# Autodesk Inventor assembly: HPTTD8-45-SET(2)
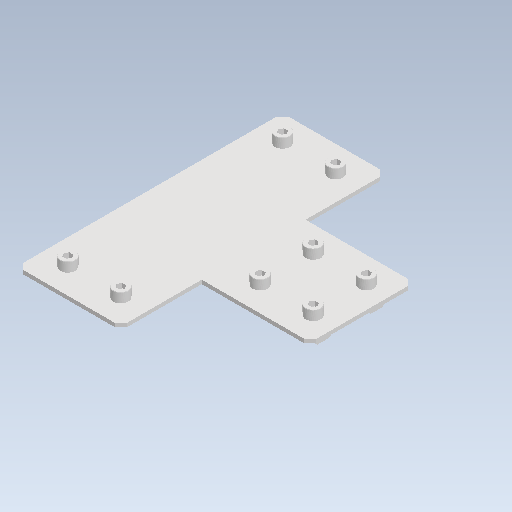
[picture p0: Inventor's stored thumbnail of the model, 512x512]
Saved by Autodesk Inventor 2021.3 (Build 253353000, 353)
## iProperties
Created: 2022-02
Part Number: HPTTD8-45-SET(2)
Document SubType Name: Assembly
Designer: kengo
Author: kengo
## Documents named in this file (4)
- C:\Users\kengo\Documents\S2S_frame\SDC345\frame_misumi_ver12\HPTTD8-45-SET(2).iam
- C:\Users\kengo\Documents\S2S_frame\SDC345\frame_misumi_ver12\HPTTD8-45.ipt
- C:\Users\kengo\Documents\S2S_frame\SDC345\frame_misumi_ver12\HNTT8-8.ipt
- C:\Users\kengo\Documents\S2S_frame\SDC345\frame_misumi_ver12\CBM8-15.ipt
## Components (17 placed, 3 different names)
1. HPTTD8-45
2. HNTT8-8
3. CBM8-15
4. HNTT8-8:1
5. CBM8-15:1
6. HNTT8-8:2
7. CBM8-15:2
8. HNTT8-8:3
9. CBM8-15:3
10. HNTT8-8:4
11. CBM8-15:4
12. HNTT8-8:5
13. CBM8-15:5
14. HNTT8-8:6
15. CBM8-15:6
16. HNTT8-8:7
17. CBM8-15:7
